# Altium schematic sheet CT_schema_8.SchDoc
size 274 x 160 mm
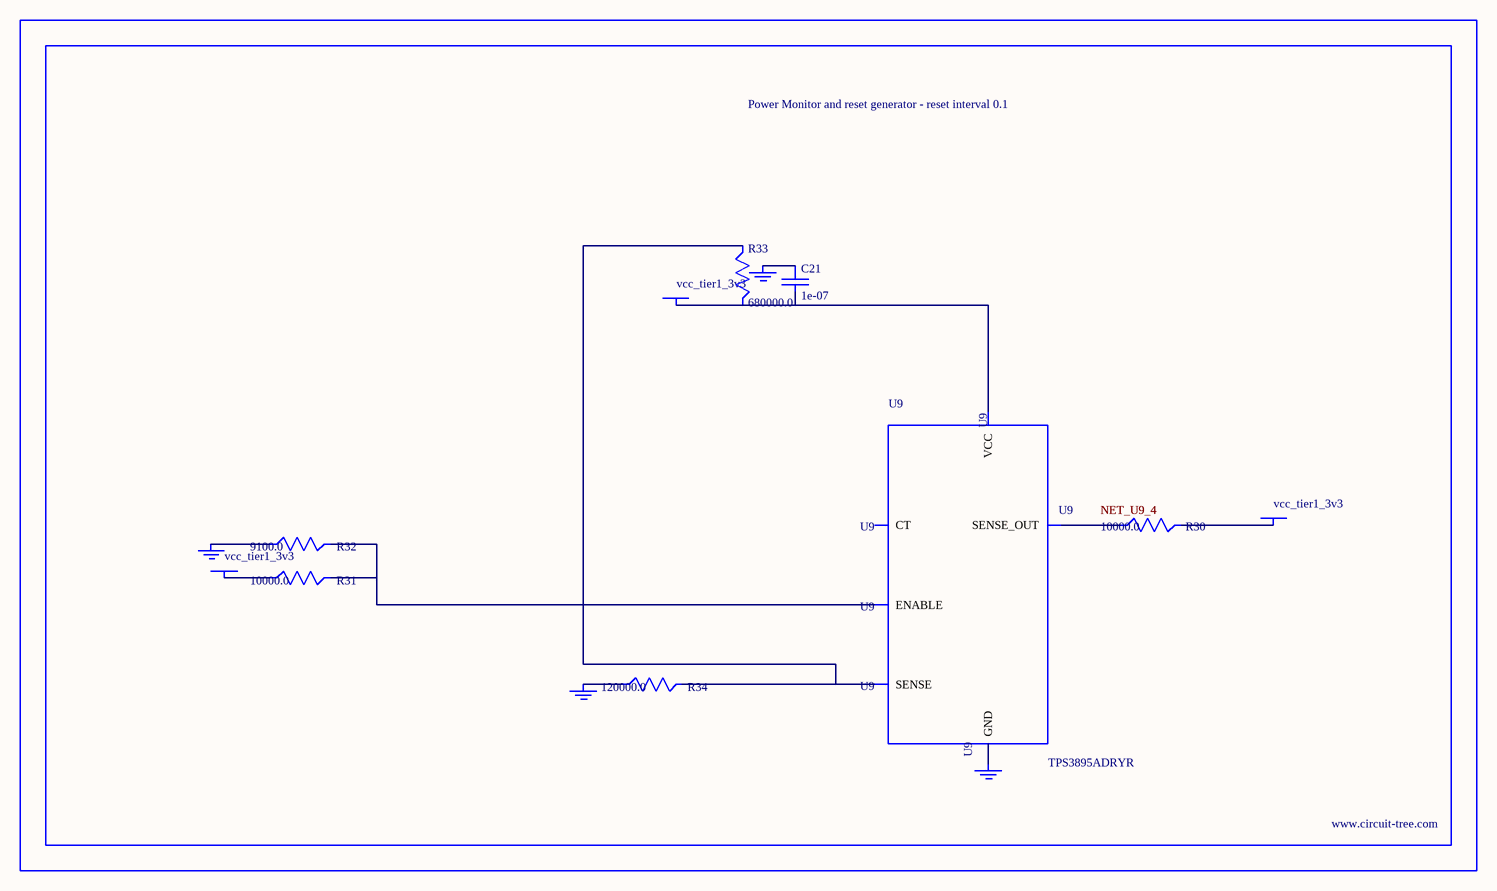
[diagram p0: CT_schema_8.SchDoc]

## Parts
BORDER7  (no value)
C21  1e-07  [C0402]
GND_INSTANCE_7_0  (no value)
GND_INSTANCE_7_1  (no value)
GND_INSTANCE_7_2  (no value)
GND_INSTANCE_7_3  (no value)
POWER_INSTANCE_7_0  vcc_tier1_3v3
POWER_INSTANCE_7_1  vcc_tier1_3v3
POWER_INSTANCE_7_2  vcc_tier1_3v3
R30  10000.0  [R0603]
R31  10000.0  [R0603]
R32  9100.0  [R0603]
R33  680000.0  [R0603]
R34  120000.0  [R0603]
U9  TPS3895ADRYR  [SON-6]

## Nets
NetC21_1: C21.1 GND_INSTANCE_7_2.0(GND)
NetC21_2: C21.2 POWER_INSTANCE_7_2.0(PWR) R33.2 U9.6(VCC)
NetGND_INSTANCE_7_0_0: GND_INSTANCE_7_0.0(GND) R32.1
NetGND_INSTANCE_7_1_0: GND_INSTANCE_7_1.0(GND) R34.1
NetGND_INSTANCE_7_3_0: GND_INSTANCE_7_3.0(GND) U9.2(GND)
NetPOWER_INSTANCE_7_0_0: POWER_INSTANCE_7_0.0(PWR) R31.1
NetPOWER_INSTANCE_7_1_0: POWER_INSTANCE_7_1.0(PWR) R30.2
NetR30_1: R30.1 U9.4(SENSE_OUT)
NetR31_2: R31.2 R32.2 U9.1(ENABLE)
NetR33_1: R33.1 R34.2 U9.3(SENSE)

Not connected (* = marked no-connect by the designer): U9 5(CT)

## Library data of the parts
BORDER7 = BORDER_PAGE7
C21 = C0402C104K3RACTU
GND_INSTANCE_7_0-GND_INSTANCE_7_3 = GND
POWER_INSTANCE_7_0-POWER_INSTANCE_7_2 = PWR
R30 R31 = RC0603JR-0710KL
R32 = RC0603JR-079K1L
R33 = RC0603JR-07680KL
R34 = RC0603JR-07120KL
